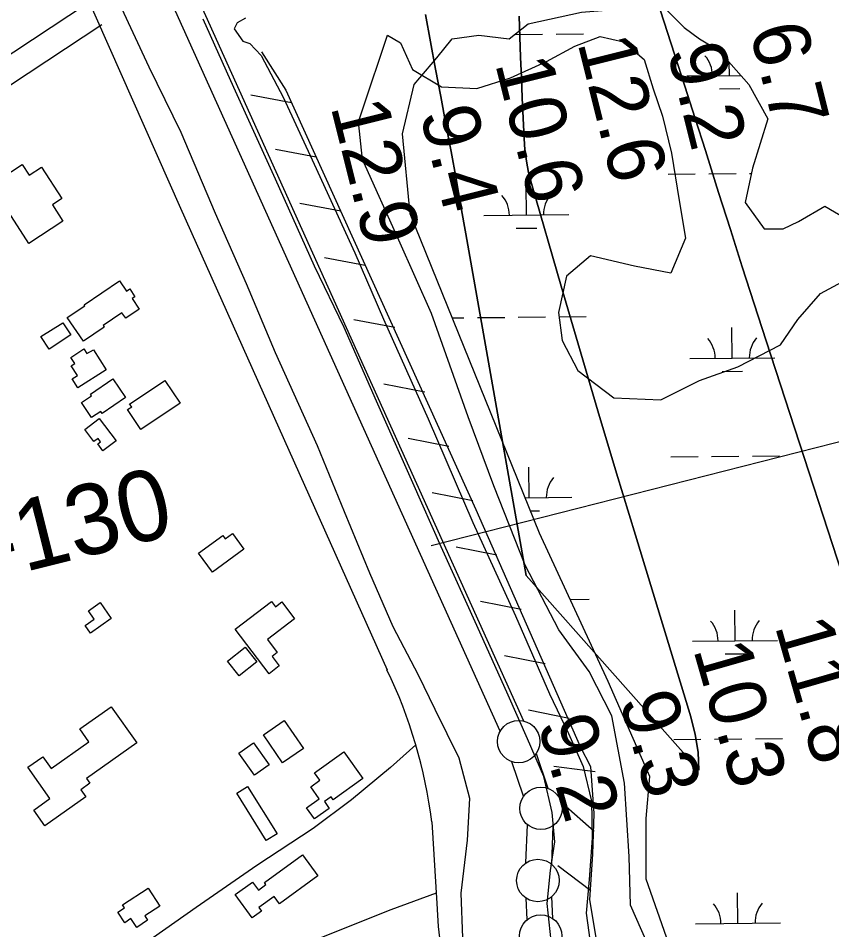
# Model space of a CAD drawing. Extents: x 3625074 to 3663148, y 511451 to 537151.
# Drawn here: x 3631259 to 3632216, y 523454 to 524527 of the extents above; entities that cross this region are included whole.
import ezdxf

# ---------------------------------------------------------------- set-up
doc = ezdxf.new("R2010")
doc.units = 0
for name, color, linetype in [('V-BLDG-OTLN', 7, 'Continuous'), ('V-FLOD-BASE', 7, 'Continuous'), ('V-LEVE-TOET', 7, 'Continuous'), ('V-RIVR-RANG', 7, 'Continuous'), ('V-RIVR-RANG-IDEN', 7, 'Continuous'), ('V-ROAD-CNTR', 7, 'Continuous'), ('V-RRAP-FSHR', 7, 'Continuous'), ('V-SITE-VEGE', 7, 'Continuous'), ('V-SURV-LINE', 7, 'Continuous'), ('V-TOPO-DPTH', 7, 'Continuous'), ('V-TOPO-MINR', 7, 'Continuous'), ('V-WETL-SWMP', 7, 'Continuous')]:
    doc.layers.add(name, color=color, linetype=linetype)

msp = doc.modelspace()

# ---------------------------------------------------------------- linework, layer by layer
at = {"layer": 'V-BLDG-OTLN'}
for points in [[(3631271.7, 524262.1), (3631226.9, 524330.8), (3631263.8, 524354.9), (3631272, 524342.4), (3631286.6, 524351.9), (3631310.7, 524315), (3631299.4, 524307.6), (3631311.9, 524288.4)], [(3631336.9, 524189.6), (3631378.5, 524217.8), (3631386.6, 524205.8), (3631390.4, 524208.4), (3631396.5, 524199.3), (3631393.1, 524197), (3631401.5, 524184.6), (3631385.8, 524173.9), (3631381.3, 524180.5), (3631359, 524165.4), (3631360.3, 524163.4), (3631336, 524146.9), (3631317, 524174.8), (3631337.5, 524188.7)], [(3631311.7, 524168.7), (3631321.1, 524154.3), (3631295.5, 524137.7), (3631286, 524152.3)], [(3631347.9, 524136.6), (3631362.8, 524113.4), (3631329.5, 524092.1), (3631322.7, 524102.7), (3631328.9, 524106.7), (3631321.7, 524117.9), (3631325.8, 524120.6), (3631321.1, 524127.9), (3631336.5, 524137.8), (3631340.1, 524132.3)], [(3631344.2, 524084.6), (3631370.6, 524102.6), (3631385.6, 524080.8), (3631357.9, 524061.9), (3631356.4, 524064.2), (3631345.6, 524057), (3631333.8, 524074.8), (3631345.5, 524082.5)], [(3631390.2, 524073), (3631431.8, 524100.8), (3631449.8, 524073.9), (3631403.6, 524043.1), (3631387.8, 524066.6), (3631392.7, 524069.8)], [(3631354.3, 524055.9), (3631374.3, 524029.5), (3631358.9, 524017.8), (3631352.7, 524026.1), (3631356.1, 524028.6), (3631353.1, 524032.6), (3631348.2, 524028.9), (3631337.5, 524043.1)], [(3631524.8, 523902.1), (3631487.6, 523875), (3631471.2, 523897.6), (3631499.9, 523918.4), (3631502.7, 523914.5), (3631511.3, 523920.7)], [(3631554.4, 523755.6), (3631514.4, 523808), (3631557.1, 523840.6), (3631561.9, 523834.4), (3631569.2, 523840), (3631584.3, 523820.2), (3631552.3, 523795.7), (3631564, 523780.4), (3631558, 523775.8), (3631566.4, 523764.8)], [(3631368.7, 523820.6), (3631344.3, 523803.3), (3631337.9, 523812.3), (3631348.5, 523819.8), (3631341.8, 523829.4), (3631355.5, 523839.2)], [(3631539.9, 523769.6), (3631519, 523753.1), (3631505.6, 523770.2), (3631526.4, 523786.7)], [(3631398.7, 523674.1), (3631339.5, 523632.1), (3631343.4, 523626.6), (3631332.8, 523619.1), (3631338.8, 523610.6), (3631290.7, 523576.5), (3631277.5, 523595), (3631296.6, 523608.6), (3631270.6, 523645.4), (3631288.3, 523657.9), (3631298.1, 523644.1), (3631342.3, 523675.4), (3631331.6, 523690.6), (3631368.5, 523716.7)], [(3631572.2, 523700.6), (3631594.9, 523667.4), (3631570.3, 523650.6), (3631547.6, 523683.8)], [(3631536.1, 523674.3), (3631554.6, 523648.3), (3631537.3, 523636.1), (3631518.8, 523662.1)], [(3631607.7, 523639.1), (3631642.1, 523663.8), (3631664.8, 523632.2), (3631629.9, 523607.2), (3631627.3, 523610.8), (3631619.4, 523605.2), (3631625.2, 523597.1), (3631607.8, 523584.6), (3631598.4, 523597.8), (3631613.3, 523608.5), (3631603.3, 523622.4), (3631614.1, 523630.2)], [(3631528.9, 523622.7), (3631563.7, 523567.2), (3631551.1, 523559.3), (3631516.3, 523614.9)], [(3631593.7, 523542.3), (3631611.6, 523517.5), (3631566.6, 523484.8), (3631560.4, 523493.4), (3631542.3, 523480.3), (3631545.3, 523476.1), (3631534.5, 523468.3), (3631514.6, 523495.7), (3631534.8, 523510.4), (3631541.8, 523500.9), (3631550.6, 523507.3), (3631548.9, 523509.7)], [(3631382.1, 523483.5), (3631412.1, 523503.1), (3631425.9, 523482), (3631408.3, 523470.5), (3631411.5, 523465.5), (3631398.6, 523457), (3631391.9, 523467.3), (3631384.6, 523462.5), (3631376.5, 523474.9), (3631384.4, 523480)]]:
    msp.add_lwpolyline(points, close=True, dxfattribs=at)
at = {"layer": 'V-FLOD-BASE'}
msp.add_lwpolyline([(3631886.1, 523441.1), (3631881.3, 523485.2), (3631885.6, 523524.1), (3631890.4, 523557.8), (3631887.5, 523592.2), (3631877.5, 523634.5), (3631858.5, 523678.8), (3631835.7, 523730.2), (3631798.8, 523812.3), (3631756.9, 523904.9), (3631723.3, 523980.4), (3631680.7, 524076.2), (3631642.6, 524162.9), (3631607.7, 524235.2), (3631561.9, 524337.5), (3631513, 524445.6), (3631476.8, 524525.8)], dxfattribs=at)
at = {"layer": 'V-LEVE-TOET'}
msp.add_line((3631527.7, 524214.6), (3631491.5, 524297.3), dxfattribs=at)
for points in [[(3631491.5, 524297.3), (3631450.9, 524392.4), (3631413.4, 524469.3), (3631378.4, 524544.3)], [(3631526.8, 524527.2), (3631517, 524521.5), (3631513.1, 524514.4), (3631523.3, 524500), (3631531.7, 524497.4), (3631545.2, 524483), (3631571.3, 524433.4), (3631607.5, 524355.2), (3631655.2, 524251), (3631688.8, 524172.8), (3631741.5, 524055.5), (3631794.2, 523933.7), (3631844.3, 523823.6), (3631884.3, 523731.7), (3631906.6, 523685.4), (3631923.7, 523646.4), (3631933.7, 523605.4), (3631934.6, 523561.9), (3631930.9, 523513.3), (3631927.2, 523473.8), (3631933.3, 523430.9), (3631951.1, 523388.6)], [(3631782.3, 523444.7), (3631780.2, 523497.3), (3631787.9, 523559.5), (3631790.4, 523608.7), (3631777.8, 523656.2), (3631749.9, 523713.6), (3631730.1, 523754), (3631700.2, 523810.7), (3631672.9, 523873.9), (3631643.1, 523946.2), (3631611.4, 524023.7), (3631561.9, 524133.1), (3631527.7, 524214.6)]]:
    msp.add_lwpolyline(points, dxfattribs=at)
at = {"layer": 'V-RIVR-RANG'}
msp.add_line((3631744.9, 523906.6), (3632908, 524202.1), dxfattribs=at)
at = {"layer": 'V-ROAD-CNTR'}
for points in [[(3631237.7, 524782.9), (3631450.2, 524303.5), (3631693.1, 523760.3)], [(3631340.8, 524544.2), (3631124.2, 524401.4), (3629820.9, 523508.8)], [(3631357.4, 524519.1), (3631141, 524376.5), (3629364.6, 523159.9)], [(3631727.1, 523671.8), (3631697.2, 523645), (3631651.4, 523607.2), (3631606.4, 523573.3), (3631539.8, 523529.8), (3631468.6, 523480.5), (3631418.3, 523445.3)], [(3631745.9, 523581.3), (3631751.8, 523485.1)], [(3631751.1, 523497.1), (3631697.6, 523477.8), (3631610.3, 523442.9), (3631551.7, 523413.7), (3631490.3, 523372.1), (3631395, 523313.3), (3631308.1, 523251.9), (3631266.3, 523223.8)]]:
    msp.add_lwpolyline(points, dxfattribs=at)
for centre, radius, start, end in [((3631169.4, 523508.6), 581, 7.193, 25.6752), ((3632105.2, 523492.5), 353.5, 181.2084, 216.2179)]:
    msp.add_arc(centre, radius, start, end, dxfattribs=at)
at = {"layer": 'V-RRAP-FSHR'}
for p, q in [((3631580.9, 524427.5), (3631532.9, 524436.5)), ((3631609.7, 524363.7), (3631561.8, 524372.7)), ((3631638.6, 524299.9), (3631590.6, 524309)), ((3631667.4, 524236.1), (3631619.4, 524245.2)), ((3631702.1, 524163.1), (3631654.2, 524172.2)), ((3631737.4, 524087.1), (3631689.5, 524096.5)), ((3631765.8, 524023.1), (3631717.9, 524032.5)), ((3631794.1, 523959.1), (3631746.2, 523968.5)), ((3631822.4, 523895.1), (3631774.5, 523904.5)), ((3631850.8, 523831.1), (3631802.9, 523840.5)), ((3631879.1, 523767.1), (3631831.2, 523776.5)), ((3631907.5, 523703), (3631859.6, 523712.5)), ((3631937.8, 523640), (3631889.4, 523646.5)), ((3631936.9, 523569.8), (3631900.4, 523602.2)), ((3631933, 523500), (3631894, 523529.4))]:
    msp.add_line(p, q, dxfattribs=at)
msp.add_lwpolyline([(3631545.4, 524487.7), (3631574.1, 524442.5), (3631797.4, 523948.7), (3631920.4, 523669.8), (3631932.3, 523646.3), (3631936.5, 523591), (3631934.9, 523543.1), (3631931.4, 523489.6), (3631939.1, 523442.7), (3631969.2, 523379.4), (3632012.2, 523310.9), (3632139.1, 523088.7), (3632169.9, 523031.2), (3632170.6, 523012.8), (3632170.6, 522981.2), (3632184, 522927.1), (3632202.3, 522887.6), (3632261.1, 522784.9)], dxfattribs=at)
at = {"layer": 'V-SITE-VEGE'}
for points in [[(3631855.6, 523883.5), (3631818.9, 523976.6), (3631788.5, 524058), (3631745.6, 524179.7), (3631706.9, 524265.7), (3631664.3, 524360.9), (3631659.6, 524405), (3631672.3, 524443.8), (3631685.6, 524482.6), (3631693.6, 524507.2), (3631709.1, 524498), (3631723.1, 524466.7), (3631757.3, 524446.2), (3631798.8, 524444.5), (3631838.5, 524457.1), (3631880.8, 524476.2), (3631914.1, 524494), (3631944, 524505.4), (3631971.2, 524499.3), (3631995.6, 524478.3), (3632006.3, 524443.8), (3632017.1, 524411.9), (3632027.7, 524368.4), (3632036.9, 524312.5), (3632044.2, 524268.3), (3632027, 524227), (3631984.2, 524235.2), (3631932.4, 524247.3), (3631904.3, 524223.6), (3631894.8, 524180.9), (3631899, 524147.8), (3631917.5, 524112.5)], [(3631917.5, 524112.5), (3631960, 524080.3), (3632015.1, 524077.9), (3632060.8, 524100.8), (3632105.7, 524116.6), (3632155.9, 524142.7), (3632176.3, 524172.3), (3632203.2, 524203.2), (3632278.8, 524244)], [(3632006.2, 523422.7), (3631979.5, 523483.3), (3631978.1, 523540.4), (3631972.5, 523626.8), (3631957.7, 523706.1), (3631930.9, 523758.2), (3631895.1, 523807.2), (3631855.6, 523883.5)]]:
    msp.add_lwpolyline(points, dxfattribs=at)
at = {"layer": 'V-SURV-LINE'}
for points in [[(3630844.1, 525939.4), (3631853.5, 523700.1)], [(3631826.1, 523687.8), (3630816.8, 525927.1)], [(3631868.6, 523661.5), (3631882.1, 523620.8)], [(3631853.6, 523611.3), (3631840.1, 523652)], [(3631856.4, 523532.8), (3631858.3, 523577.8)], [(3631888.3, 523576.5), (3631886.4, 523531.5)], [(3631857.9, 523466.1), (3631856.6, 523491.5)], [(3631886.6, 523493), (3631887.9, 523467.6)]]:
    msp.add_lwpolyline(points, dxfattribs=at)
for centre in [(3631848, 523675.7), (3631874.2, 523597.1), (3631870.6, 523512.2), (3631873.9, 523446.9)]:
    msp.add_circle(centre, 25, dxfattribs=at)
at = {"layer": 'V-TOPO-DPTH'}
for points in [[(3632360, 523378.3), (3632291.8, 523661.9), (3632283.8, 523693.5), (3632275.3, 523725), (3632266.1, 523756.3), (3632256.4, 523787.4), (3632139.1, 524147.5), (3632125, 524191.1), (3632111, 524234.6), (3632097.1, 524278.3), (3632083.2, 524321.9), (3632079.6, 524333.4), (3632067.6, 524371.3), (3632055.6, 524409.1), (3632043.5, 524447), (3632031.3, 524484.8), (3631903.1, 524882.1)], [(3631856.9, 523871.3), (3631785.9, 524273.4), (3631780.1, 524305.7), (3631774.3, 524338), (3631768.4, 524370.3), (3631762.4, 524402.5), (3631756.4, 524434.8), (3631750.3, 524467), (3631744.3, 524499.3), (3631738.3, 524531.6)], [(3631848.6, 524529.3), (3631849.4, 524505.3), (3631850.2, 524481.2), (3631851.2, 524457.3), (3631852.2, 524433.3), (3631854.3, 524385.6), (3631855.4, 524372.1), (3631857.1, 524358.8), (3631859.7, 524345.6), (3631863, 524332.5), (3631898.1, 524211.7), (3631919.5, 524138.3), (3631941.2, 524064.9), (3631963.2, 523991.7), (3631985.3, 523918.5), (3632050.6, 523704.9), (3632055.6, 523684.2), (3632059, 523663.3), (3632059.9, 523642.1), (3631856.9, 523871.3)]]:
    msp.add_lwpolyline(points, dxfattribs=at)
at = {"layer": 'V-TOPO-MINR'}
for points in [[(3631903.1, 524882.1), (3632031.3, 524484.8), (3632043.5, 524447), (3632055.6, 524409.1), (3632067.6, 524371.3), (3632079.6, 524333.4), (3632083.2, 524321.9), (3632097.1, 524278.3), (3632111, 524234.6), (3632125, 524191.1), (3632139.1, 524147.5), (3632256.4, 523787.4), (3632266.1, 523756.3), (3632275.3, 523725), (3632283.8, 523693.5), (3632291.8, 523661.9), (3632360, 523378.3)], [(3631738.3, 524531.6), (3631744.3, 524499.3), (3631750.3, 524467), (3631756.4, 524434.8), (3631762.4, 524402.5), (3631768.4, 524370.3), (3631774.3, 524338), (3631780.1, 524305.7), (3631785.9, 524273.4), (3631856.9, 523871.3)], [(3632059.9, 523642.1), (3632059, 523663.3), (3632055.6, 523684.2), (3632050.6, 523704.9), (3631985.3, 523918.5), (3631963.2, 523991.7), (3631941.2, 524064.9), (3631919.5, 524138.3), (3631898.1, 524211.7), (3631863, 524332.5), (3631859.7, 524345.6), (3631857.1, 524358.8), (3631855.4, 524372.1), (3631854.3, 524385.6), (3631852.2, 524433.3), (3631851.2, 524457.3), (3631850.2, 524481.2), (3631849.4, 524505.3), (3631848.6, 524529.3)]]:
    msp.add_lwpolyline(points, dxfattribs=at)
at = {"layer": 'V-WETL-SWMP'}
for p, q in [((3631844.1, 524507.9), (3631876.1, 524508.2)), ((3631892.1, 524508.3), (3631924.1, 524508.7)), ((3632095.9, 524459.6), (3632095.8, 524474.9)), ((3632045.9, 524459.1), (3632109.2, 524459.8)), ((3632084.1, 524444.1), (3632108.1, 524444.3)), ((3632023.7, 524343.5), (3632055.7, 524343.8)), ((3632071.7, 524344), (3632103.7, 524344.3)), ((3632119.7, 524344.4), (3632121.9, 524344.5)), ((3631857.1, 524295.4), (3631856.7, 524331.4)), ((3631807.1, 524294.9), (3631907.1, 524295.9)), ((3631845.2, 524279.8), (3631869.2, 524280.1)), ((3631770, 524174.4), (3631783.5, 524174.6)), ((3631799.5, 524174.7), (3631831.5, 524175)), ((3631847.5, 524175.2), (3631879.5, 524175.5)), ((3631895.5, 524175.7), (3631927.5, 524176)), ((3632099.3, 524127), (3632098.9, 524163)), ((3632049.3, 524126.5), (3632149.3, 524127.5)), ((3632087.4, 524111.4), (3632111.4, 524111.7)), ((3632027, 524010.8), (3632059, 524011.1)), ((3632075, 524011.3), (3632107, 524011.6)), ((3632123, 524011.8), (3632155, 524012.1)), ((3631860.4, 523962.7), (3631860.1, 523998.7)), ((3631855.7, 523962.7), (3631910.4, 523963.2)), ((3631862, 523947.3), (3631872.6, 523947.4)), ((3631908.6, 523843.1), (3631930.8, 523843.3)), ((3632102.6, 523794.3), (3632102.2, 523830.3)), ((3632052.6, 523793.8), (3632152.6, 523794.8)), ((3632090.8, 523778.8), (3632114.8, 523779)), ((3632030.4, 523678.2), (3632062.4, 523678.5)), ((3632078.4, 523678.6), (3632110.4, 523679)), ((3632126.4, 523679.1), (3632158.4, 523679.4)), ((3632105.9, 523461.7), (3632105.6, 523497.7)), ((3632055.9, 523461.2), (3632155.9, 523462.2))]:
    msp.add_line(p, q, dxfattribs=at)
for points in [[(3631859.2, 524520.6), (3631921.9, 524534.1), (3631975.6, 524538.5), (3632020.3, 524538.5), (3632042.7, 524516.2), (3632060.6, 524502.7), (3632083, 524489.3), (3632118.8, 524449), (3632141.2, 524408.7), (3632123.2, 524350.6), (3632114.3, 524310.3), (3632136.7, 524279), (3632159.1, 524279), (3632177, 524287.9), (3632208.3, 524305.8), (3632230.7, 524292.4), (3632270.9, 524261.1), (3632293.3, 524252.1), (3632338.1, 524279), (3632456.2, 524345)], [(3632024.8, 523437.6), (3631997.9, 523513.7), (3631997.9, 523585.3), (3632002.4, 523634.5), (3631953.2, 523746.4), (3631872.6, 523920.9), (3631720.5, 524296.9), (3631711.5, 524390.8), (3631725, 524449), (3631751.8, 524480.3), (3631769.7, 524502.7), (3631801, 524507.2), (3631836.8, 524502.7), (3631859.2, 524520.6)]]:
    msp.add_lwpolyline(points, dxfattribs=at)
for centre, start, end in [((3632040.7, 524459.6), 359.8032, 41.3469), ((3631801.8, 524295.3), 359.8032, 41.3469), ((3631912.3, 524296.4), 139.8032, 181.3469), ((3632044, 524126.9), 359.8032, 41.3469), ((3632154.5, 524128), 139.8032, 181.3469), ((3631915.7, 523963.7), 139.8032, 181.3469), ((3632047.4, 523794.2), 359.8032, 41.3469), ((3632157.8, 523795.4), 139.8032, 181.3469), ((3632050.7, 523461.6), 359.8032, 41.3469), ((3632161.2, 523462.7), 139.8032, 181.3469)]:
    msp.add_arc(centre, 35.2, start, end, dxfattribs=at)

# ---------------------------------------------------------------- texts
at = {"layer": 'V-RIVR-RANG'}
for s, rotation, p in [('6.7', 284.0483, (3632119.3, 524513.5)), ('12.6', 284.0483, (3631916.9, 524498.5)), ('9.2', 284.0483, (3632022.4, 524489)), ('10.6', 284.0483, (3631820, 524474)), ('12.9', 284.0483, (3631626.5, 524423.4)), ('9.4', 284.0483, (3631731.5, 524415.4)), ('11.8', 285.9683, (3632149, 523812.2)), ('10.3', 285.9683, (3632053, 523784.4)), ('9.3', 285.9683, (3631966, 523724.7)), ('9.2', 285.9683, (3631870, 523697))]:
    msp.add_text(s, height=67, rotation=rotation, dxfattribs=at).set_placement(p)
at = {"layer": 'V-RIVR-RANG-IDEN'}
msp.add_text('U-130', height=83, rotation=14.1123, dxfattribs=at).set_placement((3631152.8, 523846.5))

doc.saveas('drawing.dxf')
